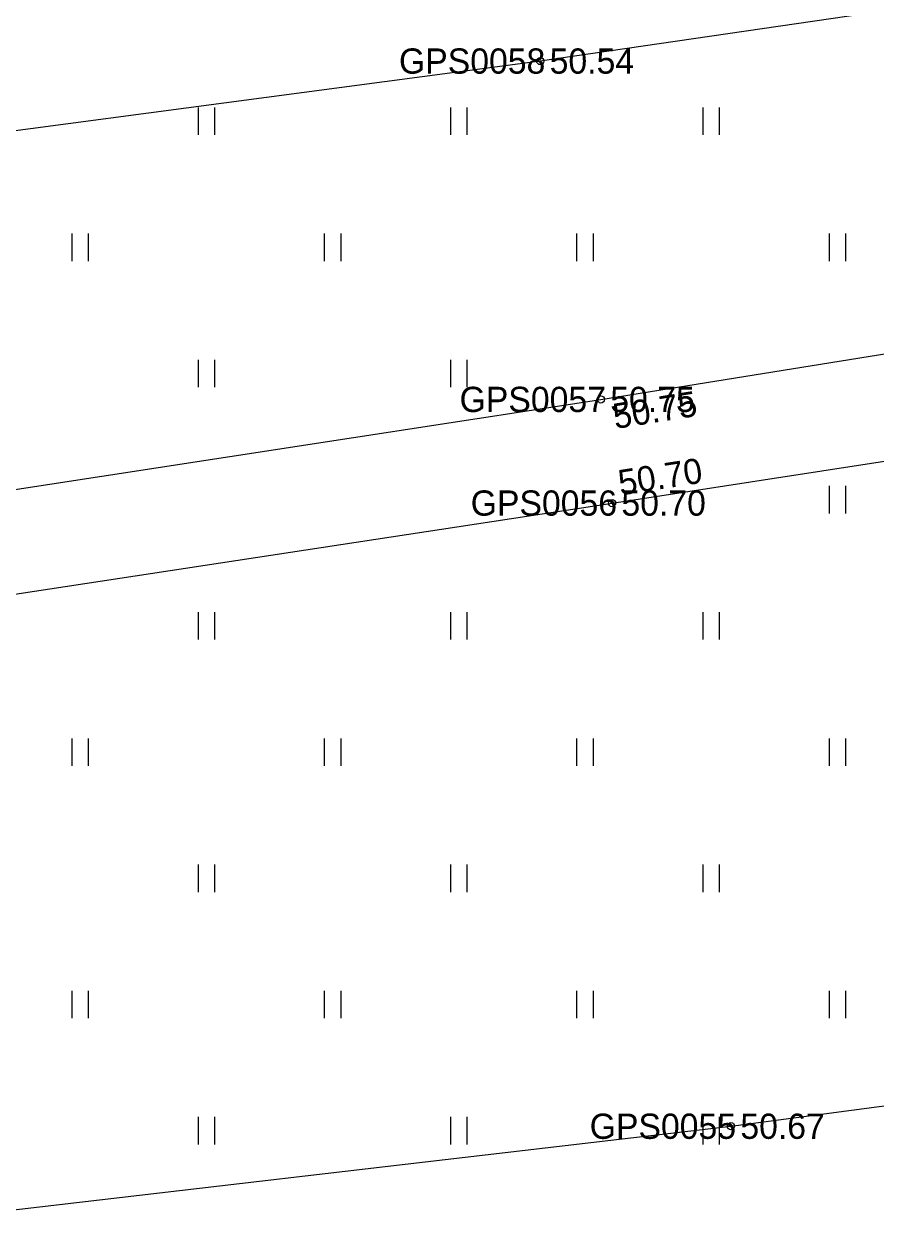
# Model space of a CAD drawing. Extents: x 563121 to 567545, y 6570841 to 6581299.
# Drawn here: x 565852.95 to 565876.57, y 6571692.22 to 6571725.69 of the extents above; entities that cross this region are included whole.
import ezdxf

# ---------------------------------------------------------------- set-up
doc = ezdxf.new("R2010")
doc.units = 0
for name, color, linetype in [('HALJASTUS', 7, 'Continuous'), ('KORGUS-EH2000', 7, 'Continuous'), ('MOOTKORG-EH2000', 7, 'Continuous'), ('MOOTMPUNKT', 7, 'Continuous'), ('MOOTNR', 7, 'Continuous'), ('MOOTPIIR', 7, 'Continuous'), ('TEE', 7, 'Continuous')]:
    doc.layers.add(name, color=color, linetype=linetype)

msp = doc.modelspace()

# ---------------------------------------------------------------- linework, layer by layer
at = {"layer": 'HALJASTUS'}
for p, q in [((565857.772, 6571723.381), (565857.772, 6571722.619)), ((565858.228, 6571723.381), (565858.228, 6571722.619)), ((565864.772, 6571723.381), (565864.772, 6571722.619)), ((565865.228, 6571723.381), (565865.228, 6571722.619)), ((565871.772, 6571723.381), (565871.772, 6571722.619)), ((565872.228, 6571723.381), (565872.228, 6571722.619)), ((565854.272, 6571719.881), (565854.272, 6571719.119)), ((565854.728, 6571719.881), (565854.728, 6571719.119)), ((565861.272, 6571719.881), (565861.272, 6571719.119)), ((565861.728, 6571719.881), (565861.728, 6571719.119)), ((565868.272, 6571719.881), (565868.272, 6571719.119)), ((565868.728, 6571719.881), (565868.728, 6571719.119)), ((565875.272, 6571719.881), (565875.272, 6571719.119)), ((565875.728, 6571719.881), (565875.728, 6571719.119)), ((565857.772, 6571716.381), (565857.772, 6571715.619)), ((565858.228, 6571716.381), (565858.228, 6571715.619)), ((565864.772, 6571716.381), (565864.772, 6571715.619)), ((565865.228, 6571716.381), (565865.228, 6571715.619)), ((565875.272, 6571712.881), (565875.272, 6571712.119)), ((565875.728, 6571712.881), (565875.728, 6571712.119)), ((565857.772, 6571709.381), (565857.772, 6571708.619)), ((565858.228, 6571709.381), (565858.228, 6571708.619)), ((565864.772, 6571709.381), (565864.772, 6571708.619)), ((565865.228, 6571709.381), (565865.228, 6571708.619)), ((565871.772, 6571709.381), (565871.772, 6571708.619)), ((565872.228, 6571709.381), (565872.228, 6571708.619)), ((565854.272, 6571705.881), (565854.272, 6571705.119)), ((565854.728, 6571705.881), (565854.728, 6571705.119)), ((565861.272, 6571705.881), (565861.272, 6571705.119)), ((565861.728, 6571705.881), (565861.728, 6571705.119)), ((565868.272, 6571705.881), (565868.272, 6571705.119)), ((565868.728, 6571705.881), (565868.728, 6571705.119)), ((565875.272, 6571705.881), (565875.272, 6571705.119)), ((565875.728, 6571705.881), (565875.728, 6571705.119)), ((565857.772, 6571702.381), (565857.772, 6571701.619)), ((565858.228, 6571702.381), (565858.228, 6571701.619)), ((565864.772, 6571702.381), (565864.772, 6571701.619)), ((565865.228, 6571702.381), (565865.228, 6571701.619)), ((565871.772, 6571702.381), (565871.772, 6571701.619)), ((565872.228, 6571702.381), (565872.228, 6571701.619)), ((565854.272, 6571698.881), (565854.272, 6571698.119)), ((565854.728, 6571698.881), (565854.728, 6571698.119)), ((565861.272, 6571698.881), (565861.272, 6571698.119)), ((565861.728, 6571698.881), (565861.728, 6571698.119)), ((565868.272, 6571698.881), (565868.272, 6571698.119)), ((565868.728, 6571698.881), (565868.728, 6571698.119)), ((565875.272, 6571698.881), (565875.272, 6571698.119)), ((565875.728, 6571698.881), (565875.728, 6571698.119)), ((565857.772, 6571695.381), (565857.772, 6571694.619)), ((565858.228, 6571695.381), (565858.228, 6571694.619)), ((565864.772, 6571695.381), (565864.772, 6571694.619)), ((565865.228, 6571695.381), (565865.228, 6571694.619)), ((565871.772, 6571695.381), (565871.772, 6571694.619)), ((565872.228, 6571695.381), (565872.228, 6571694.619))]:
    msp.add_line(p, q, dxfattribs=at)
at = {"layer": 'KORGUS-EH2000'}
for centre in [(565867.263, 6571724.668), (565868.944, 6571715.283), (565869.253, 6571712.407), (565872.552, 6571695.122)]:
    msp.add_circle(centre, 0.1, dxfattribs=at)
at = {"layer": 'MOOTMPUNKT'}
for centre in [(565867.263, 6571724.668), (565868.944, 6571715.283), (565869.253, 6571712.407), (565872.552, 6571695.122)]:
    msp.add_circle(centre, 0.1, dxfattribs=at)
at = {"layer": 'MOOTPIIR'}
msp.add_lwpolyline([(565847.666, 6571692.22), (565872.552, 6571695.122), (565896.74, 6571698.337), (565923.667, 6571701.7), (565921.225, 6571716.927), (565918.14, 6571731.716), (565901.33, 6571729.772), (565893.791, 6571728.537), (565867.263, 6571724.668), (565843.294, 6571721.486)], dxfattribs=at)
at = {"layer": 'TEE'}
for points in [[(565820.53, 6571709.209), (565844.801, 6571711.57), (565868.944, 6571715.283), (565894.174, 6571719.336)], [(565821.038, 6571705.752), (565845.152, 6571708.73), (565869.253, 6571712.407), (565894.496, 6571716.301)]]:
    msp.add_lwpolyline(points, dxfattribs=at)

# ---------------------------------------------------------------- texts
at = {"layer": 'KORGUS-EH2000'}
for s, p in [(' 50.54', (565867.263, 6571724.318)), (' 50.67', (565872.552, 6571694.772))]:
    msp.add_text(s, height=0.7, dxfattribs=at).set_placement(p)
for s, rotation, p in [(' 50.75', 9.1256, (565869.083, 6571714.419)), (' 50.70', 8.7691, (565869.226, 6571712.58))]:
    msp.add_text(s, height=0.7, rotation=rotation, dxfattribs=at).set_placement(p)
at = {"layer": 'MOOTKORG-EH2000'}
for s, p in [(' 50.54', (565867.263, 6571724.318)), (' 50.75', (565868.944, 6571714.933)), (' 50.70', (565869.253, 6571712.058)), (' 50.67', (565872.552, 6571694.772))]:
    msp.add_text(s, height=0.7, dxfattribs=at).set_placement(p)
at = {"layer": 'MOOTNR'}
for s, p in [('GPS0058 ', (565863.344, 6571724.318)), ('GPS0057 ', (565865.025, 6571714.933)), ('GPS0056 ', (565865.333, 6571712.058)), ('GPS0055 ', (565868.633, 6571694.772))]:
    msp.add_text(s, height=0.7, dxfattribs=at).set_placement(p)

doc.saveas('drawing.dxf')
